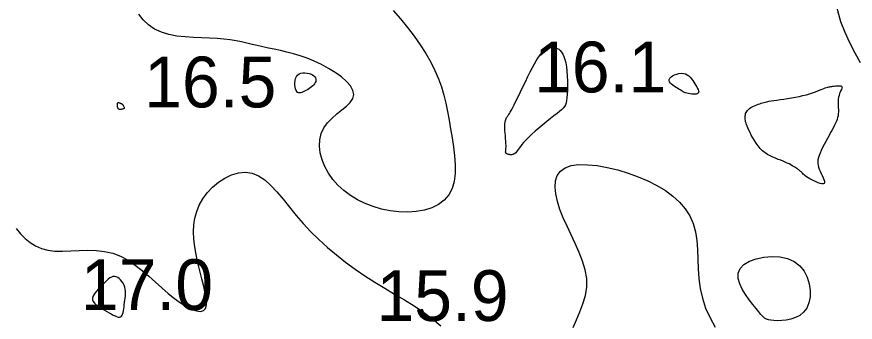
# Model space of a CAD drawing. Extents: x 3040093 to 3056816, y 408076 to 509144.
# Drawn here: x 3045513.5 to 3045596, y 434258.8 to 434288.8 of the extents above; entities that cross this region are included whole.
import ezdxf

# ---------------------------------------------------------------- set-up
doc = ezdxf.new("R2010")
doc.units = 0
doc.layers.add('V-CHAN-CONT-EL17', color=7, linetype='Continuous')
doc.layers.add('V-TOPO-SOUN-0610', color=7, linetype='Continuous')

msp = doc.modelspace()

# ---------------------------------------------------------------- linework, layer by layer
at = {"layer": 'V-CHAN-CONT-EL17'}
for points in [[(3045596.55, 434284.32), (3045596.002, 434285.266), (3045595.487, 434286.261), (3045595.02, 434287.294), (3045594.619, 434288.355), (3045594.298, 434289.432), (3045594.075, 434290.516), (3045593.965, 434291.595), (3045593.985, 434292.659), (3045594.146, 434293.696), (3045594.436, 434294.688), (3045594.841, 434295.616), (3045595.343, 434296.463), (3045595.927, 434297.209), (3045596.577, 434297.835)], [(3045550.521, 434289.457), (3045551.233, 434288.635), (3045551.922, 434287.791), (3045552.577, 434286.934), (3045553.186, 434286.072), (3045553.739, 434285.214), (3045554.225, 434284.368), (3045554.636, 434283.542), (3045554.978, 434282.731), (3045555.263, 434281.929), (3045555.5, 434281.129), (3045555.7, 434280.323), (3045555.873, 434279.507), (3045556.029, 434278.673), (3045556.179, 434277.815), (3045556.327, 434276.93), (3045556.462, 434276.032), (3045556.565, 434275.136), (3045556.62, 434274.261), (3045556.608, 434273.424), (3045556.513, 434272.641), (3045556.316, 434271.929), (3045556, 434271.306), (3045555.555, 434270.786), (3045554.992, 434270.367), (3045554.331, 434270.045), (3045553.592, 434269.816), (3045552.793, 434269.676), (3045551.953, 434269.62), (3045551.093, 434269.644), (3045550.23, 434269.745), (3045549.382, 434269.917), (3045548.56, 434270.157), (3045547.769, 434270.462), (3045547.019, 434270.828), (3045546.316, 434271.252), (3045545.669, 434271.729), (3045545.084, 434272.258), (3045544.571, 434272.833), (3045544.134, 434273.45), (3045543.782, 434274.098), (3045543.517, 434274.764), (3045543.346, 434275.435), (3045543.273, 434276.097), (3045543.303, 434276.738), (3045543.442, 434277.344), (3045543.693, 434277.904), (3045544.056, 434278.408), (3045544.499, 434278.862), (3045544.981, 434279.279), (3045545.466, 434279.669), (3045545.913, 434280.043), (3045546.283, 434280.412), (3045546.539, 434280.788), (3045546.64, 434281.181), (3045546.559, 434281.599), (3045546.311, 434282.036), (3045545.921, 434282.481), (3045545.416, 434282.924), (3045544.821, 434283.355), (3045544.162, 434283.764), (3045543.464, 434284.14), (3045542.754, 434284.473), (3045542.054, 434284.757), (3045541.368, 434284.994), (3045540.699, 434285.194), (3045540.049, 434285.363), (3045539.419, 434285.508), (3045538.812, 434285.638), (3045538.228, 434285.758), (3045537.67, 434285.877), (3045537.137, 434285.999), (3045536.62, 434286.124), (3045536.107, 434286.247), (3045535.585, 434286.364), (3045535.044, 434286.472), (3045534.472, 434286.567), (3045533.856, 434286.644), (3045533.184, 434286.701), (3045532.451, 434286.736), (3045531.67, 434286.762), (3045530.859, 434286.796), (3045530.037, 434286.853), (3045529.224, 434286.949), (3045528.437, 434287.1), (3045527.697, 434287.323), (3045527.021, 434287.632), (3045526.425, 434288.04), (3045525.913, 434288.537), (3045525.482, 434289.11)], [(3045568.246, 434258.263), (3045568.56, 434259.012), (3045568.898, 434259.784), (3045569.213, 434260.575), (3045569.46, 434261.386), (3045569.593, 434262.214), (3045569.577, 434263.059), (3045569.428, 434263.915), (3045569.173, 434264.779), (3045568.84, 434265.646), (3045568.455, 434266.512), (3045568.046, 434267.373), (3045567.641, 434268.223), (3045567.267, 434269.058), (3045566.948, 434269.873), (3045566.7, 434270.657), (3045566.537, 434271.395), (3045566.472, 434272.077), (3045566.517, 434272.688), (3045566.685, 434273.217), (3045566.991, 434273.651), (3045567.447, 434273.977), (3045568.06, 434274.185), (3045568.809, 434274.283), (3045569.667, 434274.279), (3045570.608, 434274.184), (3045571.604, 434274.007), (3045572.629, 434273.759), (3045573.656, 434273.448), (3045574.657, 434273.085), (3045575.609, 434272.678), (3045576.5, 434272.227), (3045577.322, 434271.729), (3045578.064, 434271.184), (3045578.719, 434270.589), (3045579.278, 434269.943), (3045579.731, 434269.243), (3045580.071, 434268.488), (3045580.294, 434267.678), (3045580.425, 434266.82), (3045580.493, 434265.922), (3045580.53, 434264.992), (3045580.565, 434264.039), (3045580.63, 434263.071), (3045580.753, 434262.098), (3045580.966, 434261.126), (3045581.292, 434260.165), (3045581.722, 434259.218), (3045582.242, 434258.291)], [(3045513.388, 434268.001), (3045513.831, 434267.483), (3045514.292, 434267.019), (3045514.78, 434266.616), (3045515.306, 434266.282), (3045515.88, 434266.027), (3045516.513, 434265.857), (3045517.211, 434265.776), (3045517.965, 434265.761), (3045518.76, 434265.787), (3045519.585, 434265.825), (3045520.425, 434265.85), (3045521.266, 434265.833), (3045522.097, 434265.748), (3045522.902, 434265.567), (3045523.672, 434265.272), (3045524.408, 434264.877), (3045525.114, 434264.402), (3045525.796, 434263.87), (3045526.457, 434263.302), (3045527.102, 434262.72), (3045527.735, 434262.145), (3045528.36, 434261.6), (3045528.98, 434261.104), (3045529.583, 434260.671), (3045530.154, 434260.315), (3045530.679, 434260.048), (3045531.144, 434259.883), (3045531.534, 434259.833), (3045531.836, 434259.911), (3045532.034, 434260.128), (3045532.12, 434260.493), (3045532.109, 434260.989), (3045532.02, 434261.592), (3045531.874, 434262.279), (3045531.69, 434263.029), (3045531.489, 434263.818), (3045531.29, 434264.624), (3045531.114, 434265.423), (3045530.978, 434266.197), (3045530.891, 434266.943), (3045530.859, 434267.663), (3045530.891, 434268.358), (3045530.991, 434269.03), (3045531.168, 434269.679), (3045531.426, 434270.307), (3045531.774, 434270.916), (3045532.214, 434271.503), (3045532.734, 434272.053), (3045533.317, 434272.544), (3045533.948, 434272.959), (3045534.61, 434273.276), (3045535.288, 434273.477), (3045535.965, 434273.542), (3045536.625, 434273.45), (3045537.257, 434273.19), (3045537.867, 434272.779), (3045538.465, 434272.24), (3045539.063, 434271.597), (3045539.67, 434270.876), (3045540.298, 434270.1), (3045540.958, 434269.293), (3045541.66, 434268.48), (3045542.411, 434267.68), (3045543.211, 434266.9), (3045544.052, 434266.141), (3045544.93, 434265.405), (3045545.84, 434264.693), (3045546.775, 434264.007), (3045547.731, 434263.349), (3045548.702, 434262.72), (3045549.683, 434262.12), (3045550.663, 434261.538), (3045551.632, 434260.961), (3045552.581, 434260.374), (3045553.5, 434259.764), (3045554.377, 434259.118), (3045555.204, 434258.423)]]:
    msp.add_lwpolyline(points, dxfattribs=at)
for points in [[(3045561.595, 434275.502), (3045561.593, 434275.545), (3045561.598, 434275.599), (3045561.607, 434275.666), (3045561.618, 434275.753), (3045561.628, 434275.863), (3045561.634, 434276.001), (3045561.633, 434276.171), (3045561.624, 434276.376), (3045561.608, 434276.61), (3045561.587, 434276.864), (3045561.566, 434277.128), (3045561.545, 434277.395), (3045561.528, 434277.656), (3045561.518, 434277.902), (3045561.516, 434278.125), (3045561.526, 434278.317), (3045561.545, 434278.48), (3045561.572, 434278.618), (3045561.606, 434278.734), (3045561.645, 434278.83), (3045561.687, 434278.91), (3045561.73, 434278.978), (3045561.773, 434279.036), (3045561.815, 434279.09), (3045561.859, 434279.147), (3045561.91, 434279.219), (3045561.972, 434279.316), (3045562.05, 434279.449), (3045562.148, 434279.627), (3045562.272, 434279.861), (3045562.424, 434280.163), (3045562.608, 434280.536), (3045562.818, 434280.97), (3045563.048, 434281.445), (3045563.29, 434281.945), (3045563.537, 434282.453), (3045563.782, 434282.95), (3045564.017, 434283.419), (3045564.236, 434283.843), (3045564.433, 434284.209), (3045564.61, 434284.518), (3045564.77, 434284.777), (3045564.916, 434284.993), (3045565.053, 434285.171), (3045565.182, 434285.318), (3045565.307, 434285.439), (3045565.433, 434285.542), (3045565.561, 434285.632), (3045565.692, 434285.708), (3045565.826, 434285.768), (3045565.962, 434285.812), (3045566.1, 434285.838), (3045566.241, 434285.844), (3045566.384, 434285.83), (3045566.528, 434285.794), (3045566.673, 434285.733), (3045566.818, 434285.645), (3045566.959, 434285.525), (3045567.093, 434285.369), (3045567.219, 434285.173), (3045567.334, 434284.932), (3045567.435, 434284.644), (3045567.519, 434284.302), (3045567.585, 434283.908), (3045567.633, 434283.472), (3045567.666, 434283.011), (3045567.683, 434282.54), (3045567.688, 434282.076), (3045567.681, 434281.633), (3045567.663, 434281.228), (3045567.637, 434280.877), (3045567.602, 434280.589), (3045567.554, 434280.356), (3045567.487, 434280.164), (3045567.395, 434279.999), (3045567.272, 434279.847), (3045567.112, 434279.694), (3045566.909, 434279.525), (3045566.658, 434279.328), (3045566.355, 434279.091), (3045566.012, 434278.819), (3045565.64, 434278.522), (3045565.255, 434278.209), (3045564.868, 434277.888), (3045564.494, 434277.568), (3045564.145, 434277.259), (3045563.835, 434276.968), (3045563.575, 434276.704), (3045563.36, 434276.467), (3045563.185, 434276.255), (3045563.042, 434276.067), (3045562.925, 434275.903), (3045562.827, 434275.761), (3045562.742, 434275.64), (3045562.662, 434275.538), (3045562.583, 434275.454), (3045562.504, 434275.387), (3045562.424, 434275.336), (3045562.344, 434275.298), (3045562.265, 434275.273), (3045562.187, 434275.259), (3045562.109, 434275.255), (3045562.034, 434275.258), (3045561.96, 434275.269), (3045561.889, 434275.285), (3045561.823, 434275.306), (3045561.763, 434275.332), (3045561.71, 434275.361), (3045561.665, 434275.393), (3045561.63, 434275.428), (3045561.607, 434275.464)], [(3045540.9, 434281.741), (3045540.86, 434281.926), (3045540.837, 434282.132), (3045540.836, 434282.348), (3045540.86, 434282.564), (3045540.911, 434282.769), (3045540.992, 434282.953), (3045541.107, 434283.104), (3045541.256, 434283.214), (3045541.434, 434283.285), (3045541.63, 434283.321), (3045541.836, 434283.326), (3045542.044, 434283.304), (3045542.245, 434283.26), (3045542.429, 434283.196), (3045542.588, 434283.118), (3045542.715, 434283.029), (3045542.81, 434282.931), (3045542.873, 434282.825), (3045542.908, 434282.715), (3045542.915, 434282.6), (3045542.896, 434282.484), (3045542.853, 434282.368), (3045542.787, 434282.253), (3045542.7, 434282.142), (3045542.595, 434282.035), (3045542.475, 434281.932), (3045542.345, 434281.834), (3045542.207, 434281.742), (3045542.066, 434281.657), (3045541.923, 434281.578), (3045541.784, 434281.506), (3045541.65, 434281.444), (3045541.524, 434281.393), (3045541.406, 434281.359), (3045541.296, 434281.345), (3045541.195, 434281.357), (3045541.104, 434281.399), (3045541.025, 434281.474), (3045540.956, 434281.587)], [(3045579.321, 434281.355), (3045579.203, 434281.4), (3045579.093, 434281.451), (3045578.988, 434281.507), (3045578.883, 434281.569), (3045578.773, 434281.639), (3045578.655, 434281.715), (3045578.524, 434281.799), (3045578.378, 434281.891), (3045578.224, 434281.99), (3045578.073, 434282.095), (3045577.933, 434282.206), (3045577.816, 434282.321), (3045577.731, 434282.439), (3045577.688, 434282.56), (3045577.697, 434282.683), (3045577.763, 434282.806), (3045577.881, 434282.925), (3045578.041, 434283.034), (3045578.231, 434283.129), (3045578.442, 434283.205), (3045578.664, 434283.256), (3045578.886, 434283.278), (3045579.098, 434283.265), (3045579.292, 434283.214), (3045579.468, 434283.13), (3045579.627, 434283.017), (3045579.772, 434282.883), (3045579.904, 434282.732), (3045580.026, 434282.571), (3045580.138, 434282.406), (3045580.242, 434282.242), (3045580.341, 434282.084), (3045580.429, 434281.935), (3045580.505, 434281.796), (3045580.564, 434281.669), (3045580.602, 434281.555), (3045580.615, 434281.456), (3045580.6, 434281.373), (3045580.553, 434281.307), (3045580.471, 434281.26), (3045580.36, 434281.231), (3045580.227, 434281.217), (3045580.077, 434281.217), (3045579.918, 434281.228), (3045579.757, 434281.249), (3045579.599, 434281.279), (3045579.452, 434281.314)], [(3045590.629, 434273.621), (3045590.574, 434273.671), (3045590.52, 434273.717), (3045590.464, 434273.763), (3045590.403, 434273.808), (3045590.336, 434273.856), (3045590.259, 434273.908), (3045590.171, 434273.966), (3045590.069, 434274.031), (3045589.953, 434274.104), (3045589.822, 434274.182), (3045589.675, 434274.264), (3045589.512, 434274.351), (3045589.332, 434274.44), (3045589.134, 434274.53), (3045588.919, 434274.621), (3045588.685, 434274.712), (3045588.437, 434274.806), (3045588.179, 434274.907), (3045587.916, 434275.019), (3045587.652, 434275.146), (3045587.391, 434275.292), (3045587.137, 434275.46), (3045586.895, 434275.656), (3045586.669, 434275.88), (3045586.46, 434276.127), (3045586.267, 434276.39), (3045586.091, 434276.661), (3045585.931, 434276.934), (3045585.787, 434277.201), (3045585.661, 434277.454), (3045585.551, 434277.687), (3045585.458, 434277.893), (3045585.38, 434278.075), (3045585.317, 434278.236), (3045585.267, 434278.38), (3045585.229, 434278.511), (3045585.202, 434278.632), (3045585.185, 434278.748), (3045585.177, 434278.86), (3045585.176, 434278.974), (3045585.184, 434279.088), (3045585.202, 434279.201), (3045585.232, 434279.312), (3045585.276, 434279.421), (3045585.334, 434279.527), (3045585.408, 434279.628), (3045585.5, 434279.723), (3045585.61, 434279.812), (3045585.736, 434279.895), (3045585.874, 434279.972), (3045586.02, 434280.043), (3045586.17, 434280.109), (3045586.322, 434280.169), (3045586.472, 434280.225), (3045586.615, 434280.276), (3045586.751, 434280.322), (3045586.883, 434280.366), (3045587.02, 434280.406), (3045587.166, 434280.445), (3045587.33, 434280.482), (3045587.518, 434280.52), (3045587.736, 434280.558), (3045587.991, 434280.599), (3045588.288, 434280.641), (3045588.62, 434280.688), (3045588.978, 434280.738), (3045589.355, 434280.793), (3045589.742, 434280.854), (3045590.129, 434280.921), (3045590.51, 434280.995), (3045590.875, 434281.077), (3045591.217, 434281.166), (3045591.534, 434281.262), (3045591.827, 434281.36), (3045592.096, 434281.458), (3045592.341, 434281.553), (3045592.561, 434281.642), (3045592.756, 434281.722), (3045592.927, 434281.79), (3045593.074, 434281.844), (3045593.202, 434281.886), (3045593.314, 434281.917), (3045593.418, 434281.94), (3045593.516, 434281.957), (3045593.615, 434281.971), (3045593.718, 434281.984), (3045593.832, 434281.997), (3045593.959, 434282.012), (3045594.094, 434282.028), (3045594.232, 434282.04), (3045594.364, 434282.047), (3045594.485, 434282.045), (3045594.589, 434282.03), (3045594.668, 434282.001), (3045594.716, 434281.954), (3045594.729, 434281.886), (3045594.712, 434281.799), (3045594.672, 434281.693), (3045594.616, 434281.569), (3045594.552, 434281.429), (3045594.486, 434281.275), (3045594.426, 434281.106), (3045594.379, 434280.925), (3045594.35, 434280.732), (3045594.337, 434280.531), (3045594.336, 434280.324), (3045594.342, 434280.113), (3045594.351, 434279.902), (3045594.359, 434279.693), (3045594.36, 434279.489), (3045594.352, 434279.293), (3045594.329, 434279.105), (3045594.292, 434278.924), (3045594.239, 434278.743), (3045594.171, 434278.56), (3045594.088, 434278.369), (3045593.989, 434278.167), (3045593.875, 434277.948), (3045593.744, 434277.708), (3045593.597, 434277.445), (3045593.44, 434277.163), (3045593.276, 434276.868), (3045593.112, 434276.567), (3045592.952, 434276.267), (3045592.802, 434275.973), (3045592.667, 434275.692), (3045592.553, 434275.43), (3045592.462, 434275.192), (3045592.397, 434274.975), (3045592.355, 434274.774), (3045592.337, 434274.583), (3045592.342, 434274.399), (3045592.369, 434274.216), (3045592.417, 434274.029), (3045592.486, 434273.833), (3045592.574, 434273.626), (3045592.672, 434273.413), (3045592.772, 434273.202), (3045592.863, 434273), (3045592.937, 434272.816), (3045592.984, 434272.656), (3045592.994, 434272.529), (3045592.958, 434272.442), (3045592.869, 434272.4), (3045592.736, 434272.4), (3045592.567, 434272.434), (3045592.373, 434272.497), (3045592.164, 434272.581), (3045591.95, 434272.679), (3045591.741, 434272.786), (3045591.547, 434272.894), (3045591.377, 434272.999), (3045591.23, 434273.098), (3045591.103, 434273.191), (3045590.995, 434273.279), (3045590.901, 434273.36), (3045590.82, 434273.435), (3045590.75, 434273.504), (3045590.687, 434273.566)], [(3045523.435, 434279.797), (3045523.41, 434279.843), (3045523.391, 434279.896), (3045523.376, 434279.954), (3045523.366, 434280.015), (3045523.36, 434280.076), (3045523.357, 434280.136), (3045523.357, 434280.191), (3045523.36, 434280.24), (3045523.365, 434280.283), (3045523.374, 434280.319), (3045523.386, 434280.349), (3045523.402, 434280.372), (3045523.422, 434280.388), (3045523.447, 434280.397), (3045523.476, 434280.399), (3045523.511, 434280.395), (3045523.55, 434280.384), (3045523.591, 434280.37), (3045523.633, 434280.352), (3045523.675, 434280.331), (3045523.715, 434280.31), (3045523.752, 434280.29), (3045523.785, 434280.271), (3045523.811, 434280.254), (3045523.833, 434280.239), (3045523.851, 434280.225), (3045523.866, 434280.211), (3045523.88, 434280.196), (3045523.893, 434280.179), (3045523.906, 434280.158), (3045523.922, 434280.133), (3045523.939, 434280.103), (3045523.959, 434280.07), (3045523.978, 434280.034), (3045523.997, 434279.996), (3045524.014, 434279.959), (3045524.027, 434279.923), (3045524.035, 434279.89), (3045524.037, 434279.861), (3045524.033, 434279.837), (3045524.022, 434279.817), (3045524.004, 434279.801), (3045523.981, 434279.789), (3045523.952, 434279.778), (3045523.918, 434279.768), (3045523.879, 434279.759), (3045523.836, 434279.749), (3045523.79, 434279.738), (3045523.741, 434279.727), (3045523.691, 434279.718), (3045523.64, 434279.713), (3045523.592, 434279.713), (3045523.545, 434279.72), (3045523.503, 434279.735), (3045523.466, 434279.761)], [(3045585.055, 434264.442), (3045585.594, 434264.77), (3045586.259, 434265.018), (3045587.008, 434265.178), (3045587.799, 434265.239), (3045588.591, 434265.192), (3045589.341, 434265.029), (3045590.008, 434264.739), (3045590.557, 434264.32), (3045590.986, 434263.796), (3045591.297, 434263.198), (3045591.496, 434262.556), (3045591.586, 434261.902), (3045591.572, 434261.264), (3045591.456, 434260.675), (3045591.245, 434260.165), (3045590.944, 434259.758), (3045590.571, 434259.447), (3045590.148, 434259.222), (3045589.695, 434259.068), (3045589.233, 434258.975), (3045588.783, 434258.929), (3045588.366, 434258.918), (3045588.003, 434258.93), (3045587.709, 434258.956), (3045587.471, 434259), (3045587.273, 434259.071), (3045587.096, 434259.178), (3045586.924, 434259.327), (3045586.737, 434259.529), (3045586.519, 434259.791), (3045586.253, 434260.121), (3045585.928, 434260.523), (3045585.57, 434260.985), (3045585.215, 434261.49), (3045584.897, 434262.019), (3045584.65, 434262.557), (3045584.51, 434263.085), (3045584.509, 434263.586), (3045584.684, 434264.044)], [(3045523.752, 434259.354), (3045523.821, 434259.449), (3045523.876, 434259.575), (3045523.92, 434259.726), (3045523.955, 434259.898), (3045523.985, 434260.087), (3045524.013, 434260.288), (3045524.042, 434260.498), (3045524.075, 434260.712), (3045524.107, 434260.928), (3045524.137, 434261.145), (3045524.158, 434261.363), (3045524.169, 434261.581), (3045524.164, 434261.796), (3045524.14, 434262.009), (3045524.094, 434262.217), (3045524.022, 434262.42), (3045523.926, 434262.613), (3045523.812, 434262.791), (3045523.681, 434262.949), (3045523.539, 434263.082), (3045523.388, 434263.185), (3045523.232, 434263.254), (3045523.076, 434263.284), (3045522.921, 434263.27), (3045522.768, 434263.218), (3045522.615, 434263.131), (3045522.461, 434263.017), (3045522.305, 434262.878), (3045522.146, 434262.722), (3045521.982, 434262.553), (3045521.813, 434262.376), (3045521.639, 434262.196), (3045521.466, 434262.016), (3045521.303, 434261.835), (3045521.158, 434261.655), (3045521.038, 434261.476), (3045520.953, 434261.301), (3045520.91, 434261.13), (3045520.918, 434260.964), (3045520.981, 434260.803), (3045521.095, 434260.648), (3045521.249, 434260.499), (3045521.436, 434260.355), (3045521.647, 434260.215), (3045521.872, 434260.079), (3045522.104, 434259.948), (3045522.332, 434259.82), (3045522.551, 434259.696), (3045522.757, 434259.58), (3045522.95, 434259.476), (3045523.127, 434259.388), (3045523.289, 434259.322), (3045523.433, 434259.281), (3045523.559, 434259.27), (3045523.666, 434259.293)]]:
    msp.add_lwpolyline(points, close=True, dxfattribs=at)

# ---------------------------------------------------------------- texts
at = {"layer": 'V-TOPO-SOUN-0610'}
for s, p in [('16.1 ', (3045564.393, 434281.4)), ('16.5 ', (3045526.003, 434279.92)), ('17.0 ', (3045519.773, 434259.97)), ('15.9 ', (3045548.873, 434258.89))]:
    msp.add_text(s, height=5, dxfattribs=at).set_placement(p)

doc.saveas('drawing.dxf')
